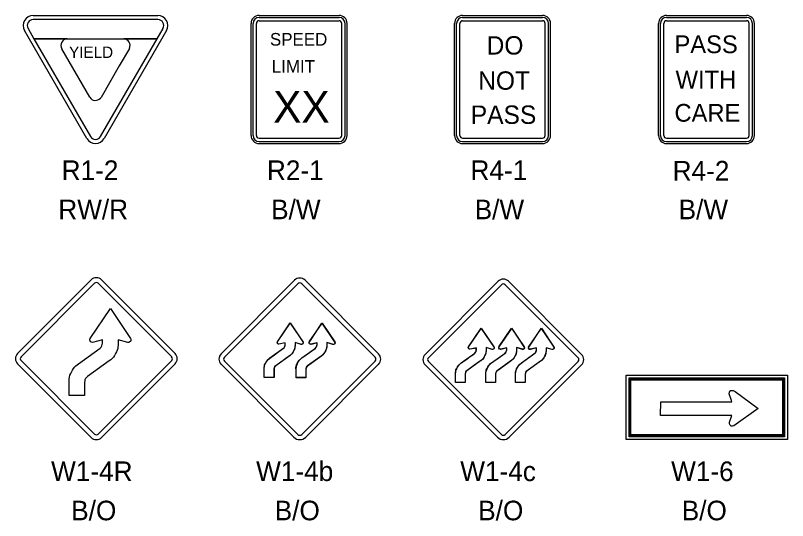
# Model space of a CAD drawing. Extents: x 10034 to 10794, y 10044 to 10499.
# Drawn here: x 10508 to 10646.1, y 10408.8 to 10499 of the extents above; entities that cross this region are included whole.
import ezdxf

# ---------------------------------------------------------------- set-up
doc = ezdxf.new("R2010")
doc.units = 0
doc.layers.add('DSIndex', color=7, linetype='Continuous')

msp = doc.modelspace()

# ---------------------------------------------------------------- linework, layer by layer
at = {"layer": 'DSIndex'}
for p, q in [((10511.2, 10499.03), (10533.51, 10499.03)), ((10533.51, 10498.3), (10511.2, 10498.3)), ((10551.6, 10499.04), (10565.9, 10499.04)), ((10551.6, 10498.68), (10565.9, 10498.68)), ((10551.6, 10498.08), (10565.9, 10498.08)), ((10587.99, 10499.04), (10602.29, 10499.04)), ((10587.99, 10498.68), (10602.29, 10498.68)), ((10587.99, 10498.08), (10602.29, 10498.08)), ((10624.46, 10499.04), (10638.76, 10499.04)), ((10624.46, 10498.68), (10638.76, 10498.68)), ((10624.46, 10498.08), (10638.76, 10498.08)), ((10510.29, 10496.73), (10511.35, 10494.88)), ((10533.35, 10494.88), (10534.42, 10496.73)), ((10550.16, 10477.58), (10550.16, 10497.61)), ((10550.52, 10477.58), (10550.52, 10497.61)), ((10551.12, 10477.58), (10551.12, 10497.61)), ((10566.38, 10477.58), (10566.38, 10497.61)), ((10566.97, 10477.58), (10566.97, 10497.61)), ((10567.33, 10477.58), (10567.33, 10497.61)), ((10586.56, 10477.58), (10586.56, 10497.61)), ((10586.56, 10477.58), (10586.56, 10497.61)), ((10586.91, 10477.58), (10586.91, 10497.61)), ((10587.51, 10477.58), (10587.51, 10497.61)), ((10602.77, 10477.58), (10602.77, 10497.61)), ((10603.36, 10477.58), (10603.36, 10497.61)), ((10603.72, 10477.58), (10603.72, 10497.61)), ((10623.03, 10477.58), (10623.03, 10497.61)), ((10623.03, 10477.58), (10623.03, 10497.61)), ((10623.38, 10477.58), (10623.38, 10497.61)), ((10623.98, 10477.58), (10623.98, 10497.61)), ((10639.24, 10477.58), (10639.24, 10497.61)), ((10639.83, 10477.58), (10639.83, 10497.61)), ((10640.19, 10477.58), (10640.19, 10497.61)), ((10520.81, 10477.04), (10509.65, 10496.36)), ((10535.05, 10496.36), (10523.9, 10477.04)), ((10511.35, 10494.88), (10522.55, 10494.88)), ((10517.28, 10494.88), (10511.35, 10494.88)), ((10511.35, 10494.88), (10519.14, 10481.39)), ((10522.55, 10494.88), (10525.73, 10494.88)), ((10523.26, 10477.4), (10533.35, 10494.88)), ((10525.73, 10494.88), (10527.31, 10494.88)), ((10527.31, 10494.88), (10533.35, 10494.88)), ((10533.35, 10494.88), (10527.43, 10494.88)), ((10521.33, 10484.44), (10516.33, 10493.1)), ((10528.4, 10493.16), (10526.6, 10490.03)), ((10526.6, 10490.03), (10523.35, 10484.4)), ((10519.14, 10481.39), (10521.44, 10477.4)), ((10551.6, 10477.1), (10565.9, 10477.1)), ((10587.99, 10477.1), (10602.29, 10477.1)), ((10624.46, 10477.1), (10638.76, 10477.1)), ((10551.6, 10476.51), (10565.9, 10476.51)), ((10551.6, 10476.15), (10565.9, 10476.15)), ((10587.99, 10476.51), (10602.29, 10476.51)), ((10587.99, 10476.15), (10602.29, 10476.15)), ((10624.46, 10476.51), (10638.76, 10476.51)), ((10624.46, 10476.15), (10638.76, 10476.15)), ((10508.42, 10438.63), (10521.57, 10451.78)), ((10509.03, 10438.04), (10522.16, 10451.17)), ((10522.84, 10451.17), (10535.97, 10438.04)), ((10523.44, 10451.78), (10536.58, 10438.63)), ((10544.8, 10438.56), (10557.95, 10451.71)), ((10545.41, 10437.96), (10558.54, 10451.1)), ((10559.23, 10451.1), (10572.36, 10437.96)), ((10559.82, 10451.71), (10572.97, 10438.56)), ((10581.28, 10438.46), (10594.35, 10451.53)), ((10581.89, 10437.87), (10594.94, 10450.92)), ((10595.62, 10450.92), (10608.67, 10437.87)), ((10596.2, 10451.53), (10609.27, 10438.46)), ((10522.16, 10424.23), (10509.03, 10437.36)), ((10535.97, 10437.36), (10522.84, 10424.23)), ((10558.54, 10424.15), (10545.41, 10437.28)), ((10572.36, 10437.28), (10559.23, 10424.15)), ((10594.94, 10424.14), (10581.89, 10437.19)), ((10608.67, 10437.19), (10595.62, 10424.14)), ((10521.57, 10423.62), (10508.42, 10436.76)), ((10536.58, 10436.76), (10523.44, 10423.62)), ((10557.81, 10423.68), (10544.8, 10436.69)), ((10572.97, 10436.69), (10559.96, 10423.68)), ((10594.35, 10423.53), (10581.28, 10436.6)), ((10609.27, 10436.6), (10596.2, 10423.53)), ((10617.94, 10423.93), (10617.94, 10434.08))]:
    msp.add_line(p, q, dxfattribs=at)
for points in [[(10517.63, 10431.13), (10517.63, 10433.51), (10517.62, 10433.74), (10517.62, 10434.08), (10517.72, 10434.41), (10517.76, 10434.74), (10517.91, 10435.07), (10518.1, 10435.41), (10518.24, 10435.64), (10518.43, 10435.93), (10518.67, 10436.22), (10518.86, 10436.41), (10519.28, 10436.75), (10523.17, 10439.55), (10523.37, 10439.78), (10523.47, 10439.97), (10523.56, 10440.21), (10523.62, 10440.48), (10523.61, 10441.06), (10521.82, 10440.6), (10521.66, 10440.64), (10521.47, 10440.73), (10521.38, 10440.87), (10521.33, 10441.06), (10521.42, 10441.35), (10521.39, 10441.31), (10525.01, 10446.66), (10528.62, 10441.31), (10528.69, 10441.16), (10528.69, 10440.92), (10528.6, 10440.78), (10528.41, 10440.68), (10528.31, 10440.59), (10528.12, 10440.59), (10526.41, 10441.09), (10526.41, 10440.48), (10526.41, 10440.21), (10526.32, 10439.68), (10526.32, 10439.49), (10526.22, 10439.21), (10526.08, 10438.92), (10525.94, 10438.64), (10525.75, 10438.26), (10525.56, 10437.97), (10525.37, 10437.78), (10525.08, 10437.5), (10524.8, 10437.29), (10520.91, 10434.49), (10520.57, 10434.17), (10520.47, 10433.89), (10520.42, 10433.6), (10520.41, 10433.51), (10520.41, 10431.13)], [(10552.51, 10434.31), (10552.51, 10435.81), (10552.51, 10435.95), (10552.51, 10436.16), (10552.57, 10436.37), (10552.6, 10436.58), (10552.69, 10436.79), (10552.81, 10437), (10552.9, 10437.15), (10553.02, 10437.33), (10553.17, 10437.51), (10553.29, 10437.63), (10553.55, 10437.84), (10556, 10439.61), (10556.13, 10439.76), (10556.19, 10439.88), (10556.25, 10440.03), (10556.28, 10440.2), (10556.28, 10440.56), (10555.15, 10440.27), (10555.05, 10440.3), (10554.93, 10440.36), (10554.87, 10440.44), (10554.84, 10440.56), (10554.9, 10440.74), (10554.88, 10440.72), (10557.16, 10444.09), (10559.44, 10440.72), (10559.48, 10440.62), (10559.48, 10440.48), (10559.42, 10440.38), (10559.3, 10440.32), (10559.24, 10440.26), (10559.12, 10440.26), (10558.04, 10440.59), (10558.04, 10440.2), (10558.05, 10440.03), (10557.99, 10439.7), (10557.99, 10439.58), (10557.93, 10439.4), (10557.84, 10439.22), (10557.75, 10439.04), (10557.63, 10438.8), (10557.51, 10438.62), (10557.39, 10438.5), (10557.21, 10438.32), (10557.03, 10438.19), (10554.58, 10436.42), (10554.36, 10436.22), (10554.31, 10436.04), (10554.27, 10435.86), (10554.27, 10435.81), (10554.27, 10434.31)], [(10554.25, 10434.32), (10552.53, 10434.34), (10552.51, 10435.38), (10552.53, 10435.96), (10552.65, 10436.65), (10552.87, 10437.06), (10553.21, 10437.56), (10553.77, 10437.99), (10554.36, 10438.39), (10554.88, 10438.82), (10555.55, 10439.29), (10556.06, 10439.66), (10556.29, 10440.13), (10556.27, 10440.55), (10555.16, 10440.32), (10555, 10440.34), (10554.87, 10440.49), (10554.88, 10440.71), (10557.16, 10444.06), (10559.48, 10440.63), (10559.44, 10440.42), (10559.37, 10440.38), (10559.26, 10440.32), (10559.18, 10440.26), (10558.07, 10440.6), (10558.05, 10440.26), (10558, 10439.82), (10557.94, 10439.48), (10557.81, 10439.15), (10557.68, 10438.9), (10557.46, 10438.57), (10557.17, 10438.27), (10554.39, 10436.29), (10554.29, 10436.13), (10554.25, 10435.87), (10554.25, 10435.28)], [(10558.21, 10434.29), (10558.21, 10435.79), (10558.2, 10435.94), (10558.2, 10436.15), (10558.26, 10436.35), (10558.3, 10436.57), (10558.39, 10436.77), (10558.5, 10436.98), (10558.59, 10437.13), (10558.71, 10437.31), (10558.86, 10437.49), (10558.98, 10437.61), (10559.25, 10437.83), (10561.7, 10439.59), (10561.83, 10439.74), (10561.89, 10439.86), (10561.95, 10440.01), (10561.98, 10440.18), (10561.98, 10440.55), (10560.85, 10440.26), (10560.75, 10440.28), (10560.63, 10440.34), (10560.57, 10440.43), (10560.54, 10440.55), (10560.6, 10440.73), (10560.58, 10440.7), (10562.86, 10444.07), (10565.13, 10440.7), (10565.18, 10440.61), (10565.18, 10440.46), (10565.12, 10440.37), (10565, 10440.31), (10564.94, 10440.25), (10564.82, 10440.25), (10563.74, 10440.57), (10563.74, 10440.18), (10563.74, 10440.01), (10563.68, 10439.68), (10563.68, 10439.56), (10563.62, 10439.38), (10563.53, 10439.2), (10563.45, 10439.02), (10563.32, 10438.78), (10563.21, 10438.6), (10563.08, 10438.48), (10562.9, 10438.3), (10562.73, 10438.17), (10560.28, 10436.4), (10560.06, 10436.21), (10560, 10436.03), (10559.97, 10435.85), (10559.96, 10435.79), (10559.96, 10434.29)], [(10559.96, 10434.31), (10558.22, 10434.33), (10558.21, 10435.82), (10558.29, 10436.38), (10558.45, 10436.84), (10558.61, 10437.13), (10558.87, 10437.48), (10559.25, 10437.83), (10559.8, 10438.21), (10560.44, 10438.68), (10561.02, 10439.1), (10561.56, 10439.48), (10561.88, 10439.8), (10561.98, 10440.21), (10561.95, 10440.52), (10560.85, 10440.27), (10560.64, 10440.36), (10560.56, 10440.58), (10560.65, 10440.77), (10562.85, 10444.05), (10565.13, 10440.59), (10565.12, 10440.41), (10565, 10440.32), (10564.92, 10440.26), (10563.74, 10440.57), (10563.73, 10440.3), (10563.69, 10439.76), (10563.61, 10439.39), (10563.41, 10438.96), (10562.98, 10438.36), (10562.8, 10438.22), (10560.09, 10436.26), (10560.05, 10436.18), (10559.95, 10435.88), (10559.94, 10435.65)], [(10586.71, 10433.44), (10586.71, 10434.93), (10586.7, 10435.08), (10586.7, 10435.28), (10586.76, 10435.49), (10586.79, 10435.7), (10586.88, 10435.91), (10587, 10436.12), (10587.09, 10436.27), (10587.21, 10436.45), (10587.36, 10436.62), (10587.48, 10436.74), (10587.74, 10436.96), (10590.18, 10438.71), (10590.3, 10438.85), (10590.36, 10438.97), (10590.42, 10439.12), (10590.45, 10439.29), (10590.45, 10439.66), (10589.33, 10439.37), (10589.23, 10439.39), (10589.11, 10439.45), (10589.05, 10439.54), (10589.02, 10439.66), (10589.08, 10439.83), (10589.06, 10439.81), (10591.32, 10443.16), (10593.59, 10439.81), (10593.63, 10439.72), (10593.63, 10439.57), (10593.57, 10439.48), (10593.45, 10439.42), (10593.39, 10439.36), (10593.27, 10439.36), (10592.2, 10439.68), (10592.2, 10439.29), (10592.2, 10439.12), (10592.14, 10438.8), (10592.14, 10438.68), (10592.09, 10438.5), (10592, 10438.32), (10591.91, 10438.14), (10591.79, 10437.9), (10591.67, 10437.72), (10591.55, 10437.61), (10591.37, 10437.43), (10591.2, 10437.3), (10588.76, 10435.54), (10588.55, 10435.34), (10588.49, 10435.16), (10588.46, 10434.99), (10588.45, 10434.93), (10588.45, 10433.44)], [(10586.73, 10433.44), (10586.74, 10434.06), (10586.75, 10434.85), (10586.76, 10435.38), (10586.82, 10435.66), (10586.94, 10435.93), (10587.1, 10436.21), (10587.37, 10436.59), (10587.71, 10436.88), (10588.23, 10437.27), (10588.75, 10437.62), (10589.19, 10437.94), (10589.51, 10438.2), (10589.8, 10438.4), (10590.12, 10438.63), (10590.27, 10438.75), (10590.41, 10438.98), (10590.47, 10439.29), (10590.48, 10439.6), (10589.35, 10439.37), (10589.17, 10439.43), (10589.05, 10439.6), (10589.12, 10439.85), (10591.34, 10443.09), (10593.63, 10439.69), (10593.63, 10439.52), (10593.58, 10439.46), (10593.46, 10439.37), (10593.42, 10439.35), (10593.34, 10439.34), (10592.22, 10439.68), (10592.23, 10439.21), (10592.16, 10438.82), (10592.12, 10438.52), (10591.93, 10438.18), (10591.78, 10437.86), (10591.54, 10437.56), (10591.25, 10437.32), (10590.86, 10437.05), (10588.58, 10435.4), (10588.53, 10435.32), (10588.44, 10435), (10588.45, 10434.66), (10588.43, 10433.44)], [(10592.15, 10433.44), (10592.15, 10434.93), (10592.14, 10435.07), (10592.14, 10435.28), (10592.2, 10435.49), (10592.23, 10435.7), (10592.32, 10435.91), (10592.44, 10436.12), (10592.53, 10436.26), (10592.65, 10436.44), (10592.8, 10436.62), (10592.92, 10436.74), (10593.18, 10436.95), (10595.62, 10438.71), (10595.74, 10438.85), (10595.8, 10438.97), (10595.86, 10439.12), (10595.9, 10439.29), (10595.89, 10439.65), (10594.77, 10439.36), (10594.67, 10439.39), (10594.56, 10439.45), (10594.49, 10439.54), (10594.46, 10439.65), (10594.52, 10439.83), (10594.5, 10439.81), (10596.77, 10443.16), (10599.03, 10439.81), (10599.07, 10439.71), (10599.07, 10439.57), (10599.01, 10439.47), (10598.9, 10439.41), (10598.84, 10439.36), (10598.72, 10439.36), (10597.64, 10439.67), (10597.64, 10439.29), (10597.65, 10439.12), (10597.59, 10438.79), (10597.59, 10438.67), (10597.53, 10438.49), (10597.44, 10438.32), (10597.35, 10438.14), (10597.23, 10437.9), (10597.11, 10437.72), (10596.99, 10437.6), (10596.81, 10437.42), (10596.64, 10437.29), (10594.2, 10435.54), (10593.99, 10435.34), (10593.93, 10435.16), (10593.9, 10434.99), (10593.89, 10434.93), (10593.89, 10433.44)], [(10593.86, 10433.43), (10592.16, 10433.44), (10592.18, 10434.71), (10592.15, 10435.14), (10592.22, 10435.48), (10592.28, 10435.61), (10592.38, 10435.89), (10592.51, 10436.18), (10592.75, 10436.51), (10593, 10436.81), (10594.36, 10437.77), (10595.19, 10438.38), (10595.74, 10438.79), (10595.9, 10439.26), (10595.91, 10439.64), (10594.77, 10439.37), (10594.61, 10439.41), (10594.5, 10439.56), (10594.52, 10439.79), (10596.78, 10443.1), (10599.08, 10439.64), (10599.01, 10439.49), (10598.92, 10439.39), (10598.78, 10439.37), (10597.65, 10439.67), (10597.64, 10439.26), (10597.62, 10438.9), (10597.57, 10438.58), (10597.42, 10438.27), (10597.12, 10437.67), (10596.75, 10437.35), (10596.25, 10437.02), (10594.04, 10435.38), (10593.93, 10435.17), (10593.87, 10434.92), (10593.87, 10434.59)], [(10597.46, 10433.42), (10597.46, 10434.9), (10597.46, 10435.05), (10597.46, 10435.26), (10597.52, 10435.47), (10597.55, 10435.67), (10597.64, 10435.88), (10597.76, 10436.09), (10597.85, 10436.24), (10597.97, 10436.42), (10598.11, 10436.6), (10598.23, 10436.72), (10598.5, 10436.93), (10600.93, 10438.68), (10601.05, 10438.83), (10601.12, 10438.95), (10601.17, 10439.1), (10601.21, 10439.27), (10601.21, 10439.63), (10600.09, 10439.34), (10599.98, 10439.36), (10599.87, 10439.42), (10599.81, 10439.51), (10599.78, 10439.63), (10599.84, 10439.81), (10599.81, 10439.78), (10602.08, 10443.13), (10604.34, 10439.78), (10604.39, 10439.69), (10604.39, 10439.54), (10604.33, 10439.45), (10604.21, 10439.39), (10604.15, 10439.33), (10604.03, 10439.33), (10602.96, 10439.65), (10602.96, 10439.27), (10602.96, 10439.1), (10602.9, 10438.77), (10602.9, 10438.65), (10602.84, 10438.47), (10602.75, 10438.29), (10602.66, 10438.11), (10602.54, 10437.88), (10602.42, 10437.7), (10602.3, 10437.58), (10602.13, 10437.4), (10601.95, 10437.27), (10599.52, 10435.52), (10599.3, 10435.32), (10599.24, 10435.14), (10599.21, 10434.96), (10599.21, 10434.9), (10599.21, 10433.42)], [(10599.19, 10433.46), (10597.46, 10433.44), (10597.47, 10434.84), (10597.5, 10435.39), (10597.64, 10435.83), (10597.8, 10436.14), (10598.08, 10436.54), (10598.45, 10436.88), (10599.63, 10437.74), (10600.67, 10438.48), (10601.09, 10438.85), (10601.22, 10439.19), (10601.21, 10439.65), (10600.09, 10439.37), (10599.9, 10439.43), (10599.81, 10439.54), (10599.82, 10439.74), (10602.07, 10443.09), (10604.36, 10439.68), (10604.33, 10439.51), (10604.21, 10439.41), (10604.04, 10439.35), (10602.96, 10439.64), (10602.95, 10439.32), (10602.89, 10438.77), (10602.72, 10438.26), (10602.49, 10437.8), (10602.09, 10437.36), (10601.69, 10437.08), (10599.38, 10435.41), (10599.19, 10434.91), (10599.21, 10434.68), (10599.18, 10434.3), (10599.18, 10433.87)], [(10623.43, 10429.98), (10636.17, 10429.96), (10636.06, 10430.22), (10635.66, 10431.41), (10635.71, 10431.73), (10635.85, 10431.99), (10636.03, 10432.03), (10636.36, 10432.03), (10636.74, 10431.83), (10640.88, 10428.81), (10636.51, 10425.69), (10636.29, 10425.66), (10636.05, 10425.62), (10635.85, 10425.83), (10635.71, 10426.06), (10635.73, 10426.35), (10636.13, 10427.57), (10623.41, 10427.53)]]:
    msp.add_lwpolyline(points, close=True, dxfattribs=at)
for points in [[(10617.23, 10434.78), (10646.11, 10434.78), (10646.11, 10423.23), (10617.23, 10423.23), (10617.23, 10434.78)], [(10617.77, 10434.25), (10645.58, 10434.25), (10645.58, 10423.76), (10617.77, 10423.76), (10617.77, 10434.25)], [(10617.82, 10434.19), (10645.52, 10434.19), (10645.52, 10423.82), (10617.82, 10423.82), (10617.82, 10434.19)], [(10617.88, 10434.13), (10645.46, 10434.13), (10645.46, 10423.88), (10617.88, 10423.88), (10617.88, 10434.13)], [(10617.94, 10434.08), (10645.4, 10434.08), (10645.4, 10423.93), (10617.94, 10423.93)], [(10618, 10434.02), (10645.34, 10434.02)], [(10618, 10434.02), (10645.34, 10434.02), (10645.34, 10423.99), (10618, 10423.99), (10618, 10434.02)], [(10618.05, 10433.96), (10645.29, 10433.96), (10645.29, 10424.05), (10618.05, 10424.05), (10618.05, 10433.96)], [(10618.11, 10433.9), (10645.23, 10433.9), (10645.23, 10424.11), (10618.11, 10424.11), (10618.11, 10433.9)]]:
    msp.add_lwpolyline(points, dxfattribs=at)
for centre, radius, start, end in [((10511.2, 10497.25), 1.78, 90, 210), ((10511.2, 10497.25), 1.05, 150, 209.9873), ((10511.2, 10497.25), 1.05, 90, 149.9981), ((10533.51, 10497.25), 1.78, 330, 90), ((10533.51, 10497.25), 1.05, 30.0019, 89.9824), ((10533.51, 10497.25), 1.05, 330, 30), ((10551.59, 10497.61), 1.43, 90, 180), ((10551.59, 10497.61), 1.07, 90, 180), ((10551.59, 10497.61), 0.477, 90, 180), ((10565.9, 10497.61), 1.43, 0, 90), ((10565.9, 10497.61), 1.07, 0, 90), ((10565.9, 10497.61), 0.477, 0, 90), ((10587.99, 10497.61), 1.43, 90, 180), ((10587.99, 10497.61), 1.07, 90, 180), ((10587.99, 10497.61), 0.477, 90, 180), ((10602.29, 10497.61), 1.43, 0, 90), ((10602.29, 10497.61), 1.07, 0, 90), ((10602.29, 10497.61), 0.477, 0, 90), ((10624.46, 10497.61), 1.43, 90, 180), ((10624.46, 10497.61), 1.07, 90, 180), ((10624.46, 10497.61), 0.477, 90, 180), ((10638.76, 10497.61), 1.43, 0, 90), ((10638.76, 10497.61), 1.07, 0, 90), ((10638.76, 10497.61), 0.477, 0, 90), ((10517.36, 10493.69), 1.19, 93.9363, 210), ((10527.34, 10493.69), 1.19, 333.1755, 86.0637), ((10522.35, 10485.05), 1.19, 210.6587, 318.1189), ((10522.35, 10485.05), 1.19, 318.1193, 327.127), ((10522.35, 10477.93), 1.05, 210, 269.9981), ((10522.35, 10477.93), 1.05, 270, 330), ((10551.59, 10477.58), 1.43, 180, 270), ((10551.59, 10477.58), 1.07, 180, 270), ((10551.59, 10477.58), 0.477, 180, 270), ((10565.9, 10477.58), 1.43, 270, 0), ((10565.9, 10477.58), 1.07, 270, 0), ((10565.9, 10477.58), 0.477, 270, 0), ((10587.99, 10477.58), 1.43, 180, 270), ((10587.99, 10477.58), 1.07, 180, 270), ((10587.99, 10477.58), 0.477, 180, 270), ((10602.29, 10477.58), 1.43, 270, 0), ((10602.29, 10477.58), 1.07, 270, 0), ((10602.29, 10477.58), 0.477, 270, 0), ((10624.46, 10477.58), 1.43, 180, 270), ((10624.46, 10477.58), 1.07, 180, 270), ((10624.46, 10477.58), 0.477, 180, 270), ((10638.76, 10477.58), 1.43, 270, 0), ((10638.76, 10477.58), 1.07, 270, 0), ((10638.76, 10477.58), 0.477, 270, 0), ((10522.35, 10477.93), 1.78, 210, 330), ((10522.5, 10450.84), 1.32, 45, 135), ((10522.5, 10450.83), 0.478, 45, 135), ((10558.88, 10450.77), 1.33, 45, 135), ((10558.88, 10450.76), 0.478, 45, 135), ((10595.28, 10450.59), 1.32, 45, 135), ((10595.28, 10450.58), 0.475, 45, 135), ((10509.36, 10437.7), 1.32, 135, 225), ((10535.64, 10437.7), 1.32, 315, 45), ((10545.74, 10437.62), 1.33, 135, 225), ((10572.03, 10437.62), 1.33, 315, 45), ((10582.22, 10437.53), 1.32, 135, 225), ((10608.34, 10437.53), 1.32, 315, 45), ((10509.37, 10437.7), 0.478, 135, 225), ((10535.63, 10437.7), 0.478, 315, 45), ((10545.74, 10437.62), 0.478, 135, 225), ((10572.02, 10437.62), 0.478, 315, 45), ((10582.22, 10437.53), 0.475, 135, 225), ((10608.33, 10437.53), 0.475, 315, 45), ((10522.5, 10424.56), 1.32, 225, 315), ((10522.5, 10424.57), 0.478, 225, 315), ((10558.88, 10424.75), 1.52, 225, 315), ((10558.88, 10424.48), 0.478, 225, 315), ((10595.28, 10424.74), 1.51, 225.2192, 314.7663), ((10595.28, 10424.48), 0.475, 225, 315)]:
    msp.add_arc(centre, radius, start, end, dxfattribs=at)

# ---------------------------------------------------------------- texts
for s, height, p in [('SPEED', 2.265, (10553.54, 10493.64)), ('DO', 3.284, (10592.29, 10492.05)), ('PASS', 3.17, (10625.89, 10492.3)), ('YIELD', 2.038, (10517.62, 10491.44)), ('LIMIT', 2.265, (10553.87, 10488.79)), ('NOT', 3.284, (10590.78, 10485.76)), ('WITH', 3.17, (10626.09, 10485.97)), ('XX', 5.662, (10554.12, 10479.89)), ('PASS', 3.284, (10589.46, 10479.66)), ('CARE', 3.17, (10625.89, 10480.05)), ('R1-2', 3.5, (10516.3, 10469.63)), ('R2-1', 3.5, (10553.01, 10469.63)), ('R4-1', 3.5, (10589.41, 10469.63)), ('R4-2', 3.5, (10625.56, 10469.54)), ('RW/R', 3.5, (10515.7, 10462.62)), ('B/W', 3.5, (10553.76, 10462.62)), ('B/W', 3.5, (10590.16, 10462.62)), ('B/W', 3.5, (10626.63, 10462.62)), ('W1-4R', 3.5, (10514.41, 10415.83)), ('W1-4b', 3.5, (10551.08, 10415.83)), ('W1-4c', 3.5, (10587.58, 10415.83)), ('W1-6', 3.5, (10625.29, 10415.83)), ('B/O', 3.5, (10518.01, 10408.82)), ('B/O', 3.5, (10554.4, 10408.82)), ('B/O', 3.5, (10590.79, 10408.82)), ('B/O', 3.5, (10627.19, 10408.82))]:
    msp.add_text(s, height=height, dxfattribs=at).set_placement(p)

doc.saveas('drawing.dxf')
